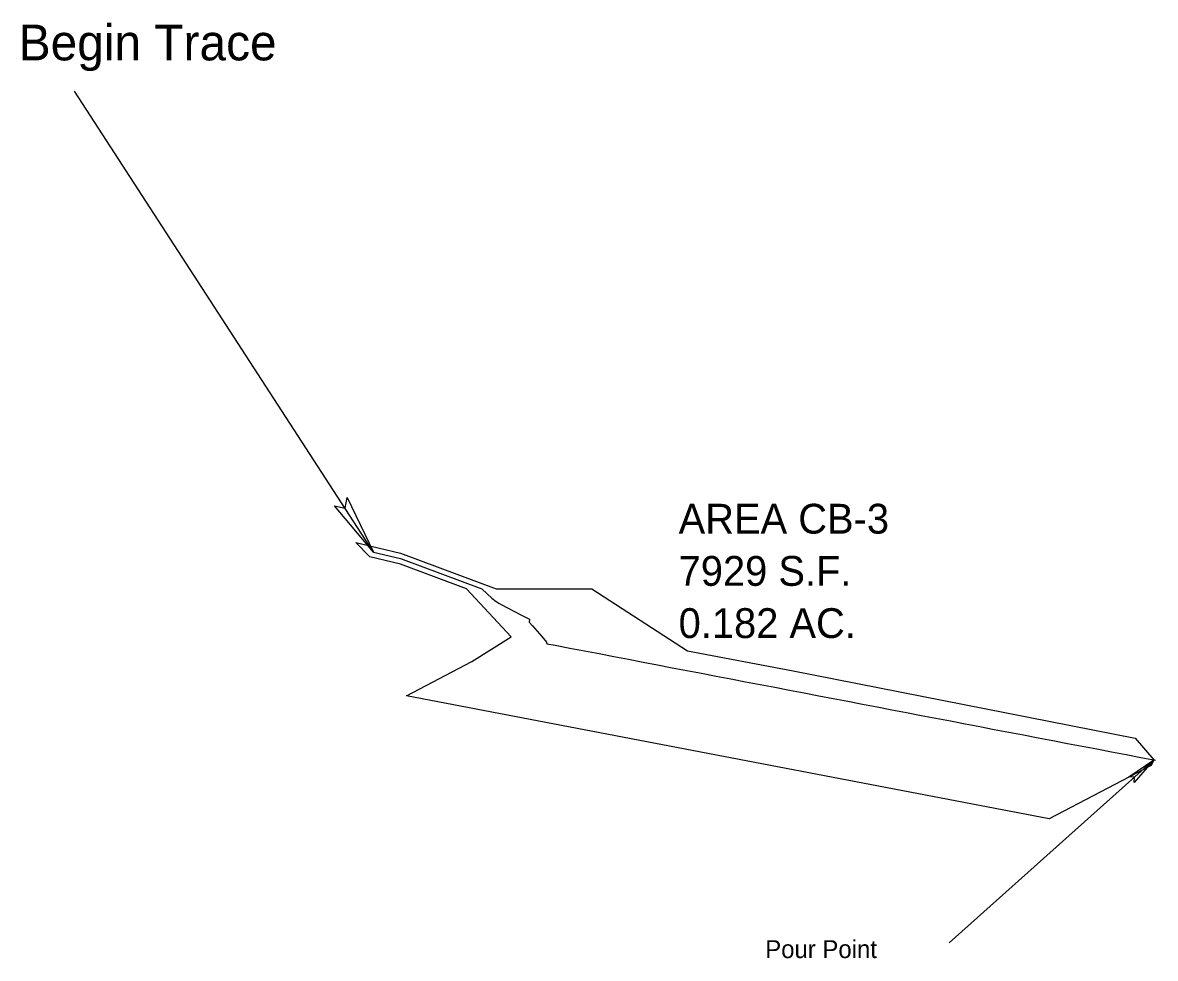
# Model space of a CAD drawing. Extents: x 2817 to 3197, y 3107 to 3421.
import ezdxf

# ---------------------------------------------------------------- set-up
doc = ezdxf.new("R2010")
doc.units = 0
for name, color, linetype in [('DESIGN - SCRATCH - User 1', 7, 'Continuous'), ('SURVEY - CENTERLINE - Preliminary', 7, 'Continuous'), ('SURVEY - CENTERLINE - Preliminary Text', 7, 'Continuous'), ('SURVEY - DRAINAGE - Area Shapes', 7, 'Continuous')]:
    doc.layers.add(name, color=color, linetype=linetype)

msp = doc.modelspace()

# ---------------------------------------------------------------- linework, layer by layer
at = {"layer": 'DESIGN - SCRATCH - User 1'}
msp.add_line((3196.4, 3173.65), (3127.69, 3112.28), dxfattribs=at)
msp.add_lwpolyline([(3196.4, 3173.65), (3189.74, 3166.02), (3189.88, 3167.82), (3188.04, 3167.93)], close=True, dxfattribs=at)
msp.add_lwpolyline([(3196.4, 3173.65), (3189.74, 3166.02), (3189.88, 3167.82), (3188.04, 3167.93), (3196.4, 3173.65)], dxfattribs=at)
at = {"layer": 'SURVEY - CENTERLINE - Preliminary'}
msp.add_lwpolyline([(2934.57, 3243.33), (2943.7, 3241.16), (2970.88, 3231.01), (2972.7, 3229.34), (2974.33, 3227.9), (2975.77, 3226.8), (2976.59, 3226.19), (2977.45, 3225.74), (2984.28, 3222.2), (2986.97, 3220.81), (2986.97, 3220.81), (2986.83, 3219.87), (2986.83, 3219.86), (2986.84, 3219.86), (2986.85, 3219.84), (2987.88, 3218.64), (2991.01, 3215), (2992.59, 3213.16), (2992.67, 3212.94), (2992.79, 3212.62), (2992.79, 3212.62), (2992.79, 3212.61), (2995.55, 3212.09), (3000.46, 3211.15), (3005.37, 3210.21), (3010.28, 3209.27), (3015.19, 3208.33), (3020.1, 3207.39), (3025.01, 3206.45), (3029.92, 3205.51), (3034.83, 3204.57), (3039.74, 3203.63), (3044.66, 3202.69), (3049.57, 3201.75), (3054.48, 3200.81), (3059.39, 3199.87), (3064.3, 3198.93), (3069.21, 3197.99), (3074.12, 3197.05), (3079.03, 3196.11), (3083.94, 3195.17), (3088.85, 3194.23), (3093.76, 3193.29), (3098.68, 3192.35), (3103.59, 3191.41), (3108.5, 3190.47), (3113.41, 3189.53), (3118.32, 3188.59), (3123.23, 3187.65), (3128.14, 3186.71), (3133.05, 3185.77), (3137.96, 3184.83), (3142.87, 3183.89), (3147.78, 3182.95), (3152.7, 3182.01), (3157.61, 3181.07), (3162.52, 3180.13), (3167.43, 3179.2), (3172.34, 3178.25), (3177.25, 3177.32), (3182.16, 3176.38), (3187.07, 3175.44), (3191.98, 3174.5), (3196.89, 3173.56)], dxfattribs=at)
at = {"layer": 'SURVEY - CENTERLINE - Preliminary Text'}
msp.add_line((2934.57, 3243.33), (2834.24, 3397.89), dxfattribs=at)
msp.add_lwpolyline([(2934.57, 3243.33), (2921.53, 3258.83), (2925.04, 3258.01), (2925.81, 3261.61)], close=True, dxfattribs=at)
msp.add_lwpolyline([(2934.57, 3243.33), (2921.53, 3258.83), (2925.04, 3258.01), (2925.81, 3261.61), (2934.57, 3243.33)], dxfattribs=at)
at = {"layer": 'SURVEY - DRAINAGE - Area Shapes'}
for p, q in [((3075.36, 3203.55), (3190.15, 3180.95)), ((3161.3, 3153.9), (2945.71, 3195.15))]:
    msp.add_line(p, q, dxfattribs=at)
for points in [[(2945.71, 3195.15), (2967.61, 3206.63), (2980.81, 3214.91), (2965.75, 3231.01), (2943.7, 3239.24), (2933.36, 3241.7), (2928.66, 3246.57)], [(2928.66, 3246.57), (2943.7, 3242.99), (2975.77, 3231.01), (3007.85, 3231.01), (3039.93, 3210.18), (3075.36, 3203.55)], [(3190.15, 3180.95), (3196.4, 3173.65), (3195.45, 3171.8), (3161.3, 3153.9)]]:
    msp.add_lwpolyline(points, dxfattribs=at)

# ---------------------------------------------------------------- texts
at = {"layer": 'DESIGN - SCRATCH - User 1'}
msp.add_text('Pour Point', height=6, dxfattribs=at).set_placement((3066.02, 3107.21))
at = {"layer": 'SURVEY - CENTERLINE - Preliminary Text'}
msp.add_text('Begin Trace', height=12, dxfattribs=at).set_placement((2815.57, 3408.18))
at = {"layer": 'SURVEY - DRAINAGE - Area Shapes'}
for s, p in [('AREA CB-3', (3036.96, 3249.51)), ('7929 S.F.', (3036.96, 3232.01)), ('0.182 AC.', (3036.96, 3214.51))]:
    msp.add_text(s, height=10, dxfattribs=at).set_placement(p)

doc.saveas('drawing.dxf')
